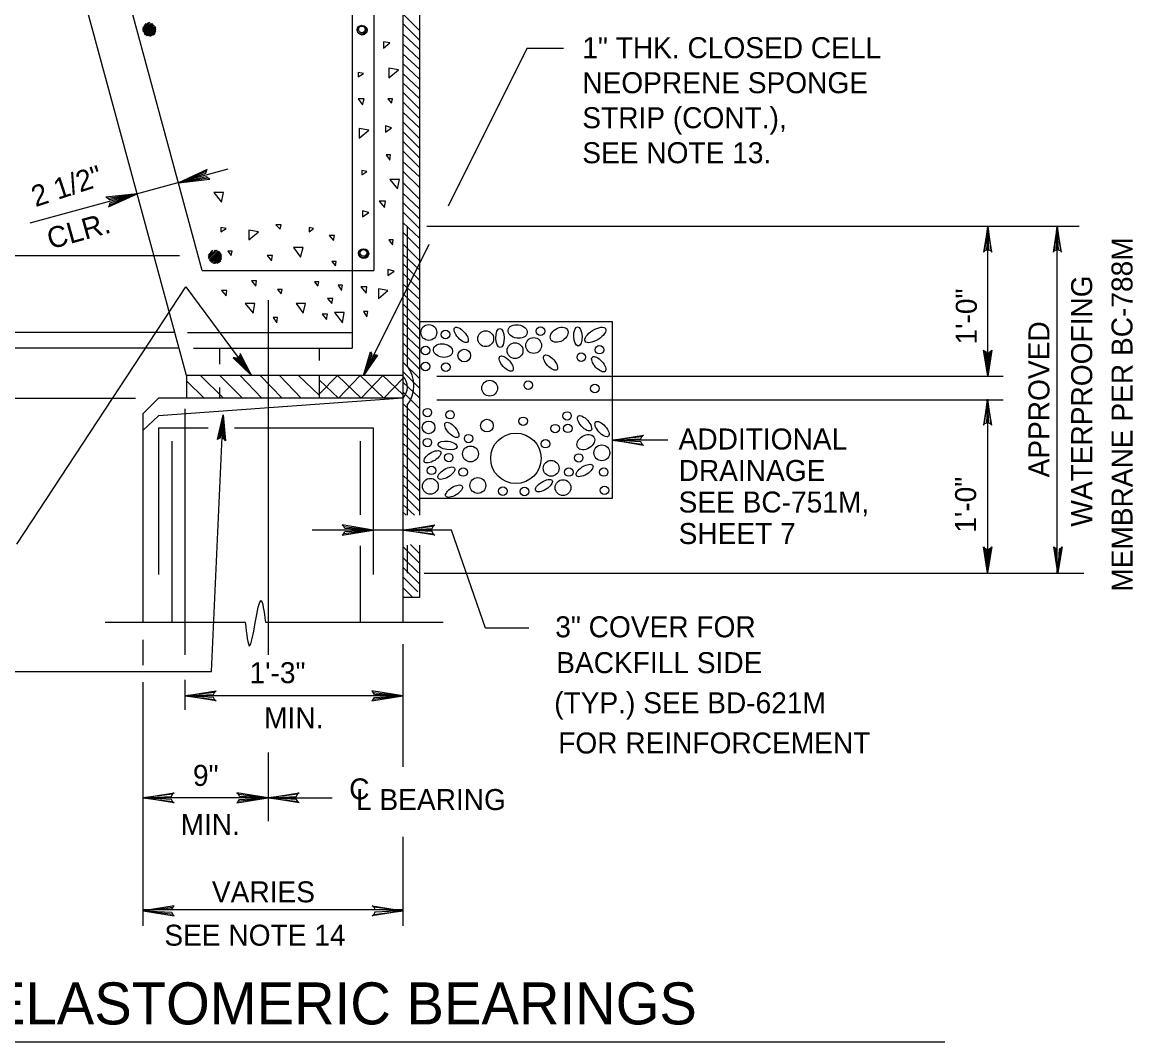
# Model space of a CAD drawing. Extents: x 640009 to 641706, y 298547 to 299735.
# Drawn here: x 640461.6 to 640620.2, y 299450.3 to 299595.9 of the extents above; entities that cross this region are included whole.
import ezdxf

# ---------------------------------------------------------------- set-up
doc = ezdxf.new("R2010")
doc.units = 0
doc.layers.add('1', color=7, linetype='Continuous')

msp = doc.modelspace()

# ---------------------------------------------------------------- linework, layer by layer
at = {"layer": '1'}
for p, q in [((640485.09, 299545.46), (640459.59, 299639.34)), ((640515.97, 299626.84), (640515.97, 299545.46)), ((640508.72, 299619.71), (640508.72, 299549.34)), ((640487.34, 299560.46), (640473.58, 299611.14)), ((640518.35, 299606.07), (640518.35, 299525.49)), ((640511.84, 299600.84), (640511.84, 299567.59)), ((640533.68, 299592.13), (640522.43, 299569.63)), ((640538.91, 299592.13), (640533.68, 299592.13)), ((640491, 299574.9), (640462.71, 299567.22)), ((640511.84, 299568.21), (640511.84, 299560.46)), ((640516.59, 299566.77), (640516.59, 299546.84)), ((640519.39, 299566.77), (640612.51, 299566.77)), ((640599.47, 299545.34), (640599.47, 299566.77)), ((640609.41, 299517.21), (640609.41, 299566.77)), ((640519.68, 299564.14), (640510.34, 299545.46)), ((640433.22, 299562.59), (640484.08, 299562.59)), ((640487.34, 299560.46), (640511.84, 299560.46)), ((640460.86, 299521.37), (640484.97, 299558.09)), ((640484.97, 299558.09), (640494.34, 299545.46)), ((640496.72, 299556.21), (640496.72, 299505.58)), ((640483.34, 299551.59), (640448.64, 299551.59)), ((640485.22, 299551.59), (640508.72, 299551.59)), ((640484.04, 299549.34), (640392.47, 299549.34)), ((640486.09, 299549.34), (640508.72, 299549.34)), ((640489.84, 299547.09), (640489.84, 299549.34)), ((640504.09, 299547.59), (640504.09, 299549.34)), ((640485.09, 299545.46), (640485.09, 299542.21)), ((640485.09, 299545.46), (640485.09, 299542.21)), ((640504.09, 299545.46), (640485.09, 299545.46)), ((640504.09, 299542.21), (640504.09, 299545.46)), ((640504.09, 299542.83), (640506.62, 299545.46)), ((640515.97, 299545.46), (640504.09, 299545.46)), ((640510.01, 299542.21), (640506.62, 299545.46)), ((640506.76, 299542.21), (640509.87, 299545.46)), ((640510.01, 299542.21), (640513.12, 299545.46)), ((640515.97, 299542.74), (640513.12, 299545.46)), ((640513.26, 299542.21), (640515.97, 299545.04)), ((640515.97, 299545.46), (640515.97, 299542.21)), ((640520.84, 299545.34), (640601.67, 299545.34)), ((640489.84, 299542.21), (640489.84, 299543.74)), ((640443.03, 299542.21), (640477.81, 299542.21)), ((640478.84, 299539.96), (640481.09, 299542.21)), ((640515.97, 299542.21), (640481.09, 299539.71)), ((640485.09, 299542.21), (640481.09, 299542.21)), ((640504.09, 299542.21), (640485.09, 299542.21)), ((640515.97, 299542.21), (640504.09, 299542.21)), ((640515.97, 299542.21), (640515.97, 299510.21)), ((640520.83, 299541.96), (640601.67, 299541.96)), ((640599.47, 299517.21), (640599.47, 299541.96)), ((640478.84, 299539.96), (640478.84, 299510.21)), ((640484.84, 299540.71), (640484.84, 299505.55)), ((640516.59, 299541.21), (640516.59, 299525.49)), ((640478.84, 299537.59), (640481.09, 299539.71)), ((640488.63, 299503.19), (640490.33, 299539.82)), ((640481.09, 299537.96), (640481.09, 299517.03)), ((640481.09, 299537.96), (640488.19, 299537.96)), ((640484.84, 299537.71), (640484.84, 299537.71)), ((640491.91, 299537.96), (640511.75, 299537.96)), ((640511.75, 299537.96), (640511.75, 299517.03)), ((640482.97, 299536.08), (640482.97, 299510.21)), ((640509.88, 299536.08), (640509.88, 299525.56)), ((640553.78, 299536.19), (640545.88, 299536.19)), ((640515.97, 299523.38), (640503.04, 299523.38)), ((640522.91, 299523.38), (640515.97, 299523.38)), ((640527.78, 299509.37), (640522.91, 299523.38)), ((640509.88, 299521.14), (640509.88, 299510.21)), ((640516.59, 299521.21), (640516.59, 299517.21)), ((640518.35, 299521.21), (640518.35, 299513.73)), ((640519, 299517.21), (640613.22, 299517.21)), ((640518.35, 299513.73), (640515.97, 299513.73)), ((640473.47, 299510.21), (640493.47, 299510.21)), ((640496.34, 299510.21), (640521.72, 299510.21)), ((640533.96, 299509.37), (640527.78, 299509.37)), ((640478.84, 299507.71), (640478.84, 299504.08)), ((640515.97, 299507.09), (640515.97, 299489.58)), ((640413.32, 299503.19), (640488.63, 299503.19)), ((640484.84, 299501.99), (640484.84, 299497.68)), ((640478.84, 299501.67), (640478.84, 299466.88)), ((640515.97, 299499.7), (640484.84, 299499.7)), ((640496.72, 299491.61), (640496.72, 299481.8)), ((640496.72, 299485.14), (640478.84, 299485.14)), ((640496.72, 299485.14), (640505.89, 299485.14)), ((640515.97, 299479.58), (640515.97, 299466.88)), ((640515.97, 299469.13), (640478.84, 299469.13)), ((640413.23, 299450.3), (640593.33, 299450.3))]:
    msp.add_line(p, q, dxfattribs=at)
for points in [[(640518.35, 299594.72), (640515.97, 299597.1)], [(640478.84, 299594.84), (640479.72, 299595.84)], [(640478.84, 299594.71), (640479.84, 299595.84)], [(640478.84, 299594.84), (640479.84, 299595.84)], [(640478.84, 299594.96), (640479.72, 299595.84)], [(640478.84, 299594.59), (640479.97, 299595.71)], [(640478.84, 299595.09), (640479.47, 299595.71)], [(640478.97, 299594.34), (640480.22, 299595.71)], [(640478.97, 299594.46), (640480.22, 299595.71)], [(640478.97, 299594.46), (640480.09, 299595.71)], [(640478.97, 299595.21), (640479.34, 299595.71)], [(640479.09, 299594.21), (640480.34, 299595.59)], [(640479.09, 299594.21), (640480.34, 299595.59)], [(640479.09, 299594.09), (640480.47, 299595.46)], [(640479.22, 299594.09), (640480.47, 299595.46)], [(640518.35, 299593.35), (640515.97, 299595.72)], [(640479.22, 299594.09), (640480.59, 299595.34)], [(640479.34, 299593.96), (640480.59, 299595.34)], [(640479.47, 299593.96), (640480.59, 299595.21)], [(640479.47, 299593.96), (640480.72, 299595.21)], [(640479.47, 299593.96), (640480.59, 299595.21)], [(640479.59, 299593.96), (640480.72, 299595.09)], [(640479.72, 299593.96), (640480.72, 299594.96)], [(640479.84, 299593.84), (640480.72, 299594.84)], [(640479.97, 299593.96), (640480.72, 299594.71)], [(640480.09, 299593.96), (640480.72, 299594.59)], [(640480.34, 299594.09), (640480.59, 299594.34)], [(640518.35, 299592), (640515.97, 299594.22)], [(640518.35, 299590.59), (640515.97, 299592.81)], [(640518.35, 299589.18), (640515.97, 299591.4)], [(640518.35, 299587.77), (640515.97, 299589.99)], [(640518.35, 299586.36), (640515.97, 299588.58)], [(640518.35, 299585), (640515.97, 299587.22)], [(640518.35, 299583.53), (640515.97, 299585.9)], [(640518.35, 299582.15), (640515.97, 299584.53)], [(640518.35, 299580.8), (640515.97, 299583.03)], [(640518.35, 299579.28), (640515.97, 299581.65)], [(640518.35, 299577.9), (640515.97, 299580.28)], [(640518.35, 299576.53), (640515.97, 299578.9)], [(640518.35, 299575.15), (640515.97, 299577.53)], [(640487.89, 299574.64), (640487.8, 299574.28), (640483.94, 299572.98), (640487.89, 299574.64), (640488.04, 299574.87), (640483.94, 299572.98), (640487.92, 299573.88), (640488.15, 299573.63), (640483.94, 299572.98), (640488.43, 299573.48), (640488.15, 299573.63)], [(640518.35, 299573.8), (640515.97, 299576.03)], [(640518.35, 299572.28), (640515.97, 299574.65)], [(640518.35, 299570.62), (640515.97, 299572.99)], [(640474.1, 299569.76), (640474.18, 299570.11), (640478.05, 299571.38), (640474.1, 299569.76), (640473.94, 299569.53), (640478.05, 299571.38), (640474.07, 299570.52), (640473.84, 299570.77), (640478.05, 299571.38), (640473.56, 299570.93), (640473.84, 299570.77)], [(640518.35, 299569.27), (640515.97, 299571.49)], [(640518.35, 299567.8), (640515.97, 299570.17)], [(640518.35, 299566.42), (640515.97, 299568.8)], [(640518.35, 299565.07), (640515.97, 299567.3)], [(640518.35, 299563.55), (640515.97, 299565.92)], [(640599.92, 299563.23), (640599.65, 299563.37), (640599.47, 299566.77), (640599.92, 299563.23), (640600.07, 299563.05), (640599.47, 299566.77), (640599.3, 299563.37), (640599.05, 299563.24), (640599.47, 299566.77), (640598.87, 299563.05), (640599.05, 299563.24)], [(640609.86, 299563.23), (640609.59, 299563.37), (640609.41, 299566.77), (640609.86, 299563.23), (640610.01, 299563.05), (640609.41, 299566.77), (640609.24, 299563.37), (640608.99, 299563.24), (640609.41, 299566.77), (640608.81, 299563.05), (640608.99, 299563.24)], [(640518.35, 299561.88), (640515.97, 299564.26)], [(640488.22, 299562.09), (640489.47, 299563.34)], [(640488.22, 299562.21), (640489.34, 299563.34)], [(640488.22, 299562.21), (640489.22, 299563.34)], [(640488.22, 299562.34), (640489.22, 299563.34)], [(640488.22, 299562.59), (640488.84, 299563.34)], [(640488.22, 299562.46), (640488.84, 299563.09)], [(640488.34, 299561.84), (640489.72, 299563.21)], [(640488.34, 299561.96), (640489.59, 299563.21)], [(640488.34, 299561.96), (640489.59, 299563.21)], [(640488.47, 299561.71), (640489.84, 299563.09)], [(640488.47, 299561.84), (640489.72, 299563.09)], [(640488.59, 299561.59), (640489.97, 299562.96)], [(640488.59, 299561.71), (640489.84, 299562.96)], [(640488.72, 299561.59), (640489.97, 299562.84)], [(640488.72, 299561.59), (640489.97, 299562.84)], [(640488.72, 299561.59), (640489.97, 299562.71)], [(640488.84, 299561.46), (640490.09, 299562.71)], [(640488.97, 299561.46), (640490.09, 299562.59)], [(640489.09, 299561.46), (640490.09, 299562.46)], [(640489.09, 299561.46), (640490.09, 299562.34)], [(640489.22, 299561.46), (640490.09, 299562.21)], [(640518.35, 299560.53), (640515.97, 299562.76)], [(640489.47, 299561.46), (640490.09, 299562.09)], [(640489.59, 299561.59), (640489.97, 299561.84)], [(640518.35, 299559.06), (640515.97, 299561.43)], [(640518.35, 299557.68), (640515.97, 299560.06)], [(640518.35, 299556.33), (640515.97, 299558.56)], [(640518.35, 299554.81), (640515.97, 299557.18)], [(640518.35, 299553.32), (640515.97, 299555.7)], [(640518.35, 299552), (640515.97, 299554.37)], [(640518.35, 299550.62), (640515.97, 299553)], [(640518.35, 299549.27), (640515.97, 299551.5)], [(640518.35, 299547.75), (640515.97, 299550.12)], [(640491.97, 299547.96), (640492.22, 299547.96), (640494.34, 299545.46), (640491.97, 299547.96), (640491.72, 299547.96), (640494.34, 299545.46), (640492.59, 299548.21), (640492.72, 299548.34), (640494.34, 299545.46), (640492.72, 299548.59), (640492.72, 299548.34)], [(640512.22, 299548.34), (640511.97, 299548.34), (640510.34, 299545.46), (640512.22, 299548.34), (640512.34, 299548.34), (640510.34, 299545.46), (640511.59, 299548.46), (640511.47, 299548.59), (640510.34, 299545.46), (640511.34, 299548.84), (640511.47, 299548.59)], [(640518.35, 299546.37), (640515.97, 299548.75)], [(640599.92, 299548.88), (640599.65, 299548.73), (640599.47, 299545.34), (640599.92, 299548.88), (640600.07, 299549.05), (640599.47, 299545.34), (640599.3, 299548.73), (640599.05, 299548.86), (640599.47, 299545.34), (640598.87, 299549.05), (640599.05, 299548.86)], [(640518.35, 299545), (640515.97, 299547.37)], [(640487.59, 299542.21), (640485.09, 299544.71)], [(640490.34, 299542.21), (640487.09, 299545.46)], [(640493.09, 299542.21), (640489.84, 299545.46)], [(640495.84, 299542.21), (640492.72, 299545.46)], [(640498.72, 299542.21), (640495.59, 299545.46)], [(640501.47, 299542.21), (640498.34, 299545.46)], [(640504.09, 299542.59), (640501.09, 299545.46)], [(640506.76, 299542.21), (640504.09, 299544.76)], [(640513.26, 299542.21), (640509.87, 299545.46)], [(640518.35, 299543.62), (640515.97, 299546)], [(640518.35, 299542.27), (640515.97, 299544.5)], [(640518.35, 299540.75), (640515.97, 299543.12)], [(640599.9, 299538.51), (640599.64, 299538.66), (640599.46, 299542.05), (640599.9, 299538.51), (640600.06, 299538.34), (640599.46, 299542.05), (640599.29, 299538.66), (640599.04, 299538.53), (640599.46, 299542.05), (640598.85, 299538.34), (640599.04, 299538.53)], [(640518.35, 299539.09), (640515.97, 299541.47)], [(640518.35, 299537.74), (640515.97, 299539.97)], [(640489.71, 299536.43), (640489.92, 299536.56), (640490.33, 299539.82), (640489.71, 299536.43), (640489.5, 299536.29), (640490.33, 299539.82), (640490.26, 299536.49), (640490.5, 299536.35), (640490.33, 299539.82), (640490.64, 299536.14), (640490.5, 299536.35)], [(640518.35, 299536.27), (640515.97, 299538.64)], [(640518.35, 299534.89), (640515.97, 299537.27)], [(640550.12, 299535.65), (640549.95, 299535.97), (640545.88, 299536.19), (640550.12, 299535.65), (640550.33, 299535.47), (640545.88, 299536.19), (640549.95, 299536.39), (640550.11, 299536.69), (640545.88, 299536.19), (640550.33, 299536.91), (640550.11, 299536.69)], [(640518.35, 299533.54), (640515.97, 299535.77)], [(640518.35, 299532.02), (640515.97, 299534.39)], [(640518.35, 299530.35), (640515.97, 299532.73)], [(640518.35, 299529), (640515.97, 299531.23)], [(640518.35, 299527.53), (640515.97, 299529.9)], [(640518.35, 299526.07), (640515.97, 299528.45)], [(640516.42, 299525.49), (640515.9, 299525.98)], [(640517.62, 299525.49), (640515.97, 299527.03)], [(640507.51, 299522.85), (640507.68, 299523.16), (640511.75, 299523.38), (640507.51, 299522.85), (640507.3, 299522.66), (640511.75, 299523.38), (640507.68, 299523.58), (640507.53, 299523.89), (640511.75, 299523.38), (640507.3, 299524.11), (640507.53, 299523.89)], [(640520.31, 299522.85), (640520.14, 299523.16), (640516.07, 299523.38), (640520.31, 299522.85), (640520.52, 299522.66), (640516.07, 299523.38), (640520.14, 299523.58), (640520.3, 299523.89), (640516.07, 299523.38), (640520.52, 299524.11), (640520.3, 299523.89)], [(640518.35, 299518.64), (640515.97, 299521.01)], [(640518.41, 299519.97), (640517.08, 299521.3)], [(640599.9, 299520.79), (640599.64, 299520.64), (640599.46, 299517.25), (640599.9, 299520.79), (640600.06, 299520.96), (640599.46, 299517.25), (640599.29, 299520.64), (640599.04, 299520.77), (640599.46, 299517.25), (640598.85, 299520.96), (640599.04, 299520.77)], [(640609.96, 299520.79), (640609.7, 299520.64), (640609.51, 299517.25), (640609.96, 299520.79), (640610.12, 299520.96), (640609.51, 299517.25), (640609.35, 299520.64), (640609.09, 299520.77), (640609.51, 299517.25), (640608.91, 299520.96), (640609.09, 299520.77)], [(640518.2, 299517.25), (640515.97, 299519.48)], [(640518.35, 299515.71), (640515.97, 299518.08)], [(640518.13, 299514.54), (640515.97, 299516.7)], [(640517.39, 299513.73), (640515.97, 299515.15)], [(640489.09, 299499.16), (640488.92, 299499.48), (640484.84, 299499.7), (640489.09, 299499.16), (640489.3, 299498.97), (640484.84, 299499.7), (640488.92, 299499.9), (640489.07, 299500.2), (640484.84, 299499.7), (640489.3, 299500.42), (640489.07, 299500.2)], [(640511.73, 299499.16), (640511.9, 299499.48), (640515.97, 299499.7), (640511.73, 299499.16), (640511.52, 299498.97), (640515.97, 299499.7), (640511.9, 299499.9), (640511.74, 299500.2), (640515.97, 299499.7), (640511.52, 299500.42), (640511.74, 299500.2)], [(640483.09, 299484.61), (640482.92, 299484.92), (640478.84, 299485.14), (640483.09, 299484.61), (640483.3, 299484.42), (640478.84, 299485.14), (640482.92, 299485.34), (640483.07, 299485.65), (640478.84, 299485.14), (640483.3, 299485.87), (640483.07, 299485.65)], [(640492.48, 299484.61), (640492.65, 299484.92), (640496.72, 299485.14), (640492.48, 299484.61), (640492.27, 299484.42), (640496.72, 299485.14), (640492.65, 299485.34), (640492.49, 299485.65), (640496.72, 299485.14), (640492.27, 299485.87), (640492.49, 299485.65)], [(640500.96, 299484.61), (640500.79, 299484.92), (640496.72, 299485.14), (640500.96, 299484.61), (640501.17, 299484.42), (640496.72, 299485.14), (640500.79, 299485.34), (640500.95, 299485.65), (640496.72, 299485.14), (640501.17, 299485.87), (640500.95, 299485.65)], [(640483.13, 299469.53), (640482.96, 299469.22), (640478.89, 299468.99), (640483.13, 299469.53), (640483.34, 299469.72), (640478.89, 299468.99), (640482.96, 299468.79), (640483.12, 299468.49), (640478.89, 299468.99), (640483.34, 299468.27), (640483.12, 299468.49)], [(640511.81, 299469.53), (640511.98, 299469.22), (640516.05, 299468.99), (640511.81, 299469.53), (640511.59, 299469.72), (640516.05, 299468.99), (640511.98, 299468.79), (640511.82, 299468.49), (640516.05, 299468.99), (640511.59, 299468.27), (640511.82, 299468.49)]]:
    msp.add_lwpolyline(points, dxfattribs=at)
for points in [[(640513.22, 299592.21), (640514.09, 299592.96), (640513.22, 299593.09)], [(640513.97, 299587.96), (640515.34, 299589.09), (640513.97, 299589.34)], [(640509.59, 299588.09), (640510.34, 299588.59), (640509.59, 299588.71)], [(640509.59, 299584.96), (640510.22, 299584.09), (640510.47, 299584.96)], [(640513.84, 299584.96), (640514.34, 299584.34), (640514.47, 299584.96)], [(640509.72, 299579.34), (640511.09, 299580.46), (640509.72, 299580.71)], [(640513.47, 299580.21), (640514.34, 299580.84), (640513.47, 299581.09)], [(640513.59, 299576.96), (640514.09, 299576.21), (640514.22, 299576.96)], [(640510.09, 299574.09), (640510.84, 299574.59), (640510.09, 299574.71)], [(640514.09, 299573.46), (640515.22, 299572.09), (640515.47, 299573.46)], [(640488.97, 299571.59), (640490.09, 299570.21), (640490.34, 299571.59)], [(640512.59, 299570.34), (640513.34, 299569.46), (640513.47, 299570.34)], [(640510.22, 299568.09), (640511.09, 299568.71), (640510.22, 299568.96)], [(640497.84, 299566.96), (640498.47, 299566.34), (640498.59, 299566.96)], [(640489.97, 299565.96), (640490.72, 299566.46), (640489.97, 299566.59)], [(640493.97, 299564.84), (640495.34, 299565.96), (640493.97, 299566.21)], [(640502.59, 299565.96), (640503.22, 299566.46), (640502.59, 299566.59)], [(640505.47, 299565.46), (640506.09, 299564.71), (640506.22, 299565.46)], [(640500.34, 299563.71), (640501.34, 299562.34), (640501.72, 299563.71)], [(640513.97, 299564.84), (640514.47, 299564.09), (640514.59, 299564.84)], [(640490.97, 299563.21), (640491.47, 299562.59), (640491.59, 299563.21)], [(640496.59, 299562.59), (640497.22, 299561.84), (640497.34, 299562.59)], [(640505.84, 299561.71), (640506.34, 299561.09), (640506.47, 299561.71)], [(640513.84, 299559.71), (640514.72, 299560.34), (640513.84, 299560.59)], [(640494.34, 299558.96), (640494.97, 299558.21), (640495.09, 299558.96)], [(640490.09, 299557.59), (640490.72, 299556.84), (640490.84, 299557.59)], [(640498.09, 299557.71), (640498.59, 299557.09), (640498.72, 299557.71)], [(640503.34, 299558.84), (640503.84, 299558.21), (640503.97, 299558.84)], [(640506.72, 299558.34), (640507.22, 299557.59), (640507.34, 299558.34)], [(640509.97, 299558.09), (640510.72, 299557.21), (640510.84, 299558.09)], [(640512.47, 299556.46), (640513.84, 299557.59), (640512.47, 299557.84)], [(640505.22, 299556.46), (640505.84, 299555.71), (640505.97, 299556.46)], [(640493.47, 299555.71), (640494.59, 299554.34), (640494.84, 299555.71)], [(640500.72, 299555.71), (640501.72, 299554.34), (640502.09, 299555.71)], [(640504.47, 299554.21), (640505.09, 299553.46), (640505.22, 299554.21)], [(640506.22, 299554.46), (640507.34, 299552.96), (640507.59, 299554.46)], [(640510.34, 299554.59), (640510.84, 299553.84), (640510.97, 299554.59)], [(640497.47, 299553.71), (640497.97, 299552.96), (640498.09, 299553.71)], [(640545.88, 299553.11), (640518.35, 299553.11), (640518.35, 299527.92), (640545.88, 299527.92)]]:
    msp.add_lwpolyline(points, close=True, dxfattribs=at)
for centre, radius in [((640510.06, 299594.82), 0.636), ((640510.17, 299594.76), 0.693), ((640510.12, 299594.88), 0.474), ((640510.29, 299562.9), 0.636), ((640510.4, 299562.84), 0.693), ((640510.35, 299562.95), 0.474), ((640519.68, 299551.6), 1.13), ((640522.05, 299551.3), 0.605), ((640527.8, 299550.7), 1.13), ((640535.63, 299551.77), 0.605), ((640519.2, 299549.02), 0.605), ((640531.99, 299549), 1.13), ((640534.65, 299549.74), 1.13), ((640544.05, 299549.13), 0.605), ((640524.74, 299548.3), 0.9), ((640541.44, 299548.06), 0.605), ((640519.2, 299546.74), 0.605), ((640522.1, 299546.63), 0.605), ((640528.36, 299543.63), 1.13), ((640533.88, 299544.07), 0.605), ((640543.39, 299543.59), 0.605), ((640519.47, 299540.15), 0.605), ((640522.71, 299539.85), 0.605), ((640539.42, 299539.67), 0.605), ((640519.64, 299538.04), 0.9), ((640527.97, 299538.29), 0.9), ((640533.15, 299538.91), 0.605), ((640537.71, 299537.86), 0.605), ((640539.52, 299537.9), 0.605), ((640525.36, 299536.44), 0.605), ((640532.11, 299533.62), 3.6), ((640519.47, 299535.87), 0.605), ((640525.63, 299534.25), 1.13), ((640536.33, 299535.7), 0.605), ((640544.38, 299534.41), 1.13), ((640522.52, 299533.72), 0.605), ((640541.08, 299533.68), 0.605), ((640520.07, 299531.9), 0.605), ((640524.58, 299531.66), 0.605), ((640537.15, 299532.2), 1.13), ((640539.66, 299531.66), 0.605), ((640544.65, 299531.66), 0.605), ((640519.9, 299529.63), 1.13), ((640526.67, 299529.75), 1.13), ((640538.84, 299529.44), 1.13), ((640530.24, 299528.94), 0.605), ((640533.34, 299528.88), 0.605), ((640544.76, 299529.05), 0.605)]:
    msp.add_circle(centre, radius, dxfattribs=at)
msp.add_arc((640513.09, 299544.01), 4.47, 321.0382, 38.9618, dxfattribs=at)
for centre, major_axis, ratio in [((640532.36, 299551.73), (1.36, -0.2), 0.696126), ((640524.3, 299551.25), (0.91, -1.02), 0.438009), ((640529.84, 299550.8), (0.04, -1.37), 0.438009), ((640538.29, 299551.27), (1.17, 0.72), 0.696126), ((640540.96, 299551.03), (0.04, -1.37), 0.438009), ((640543.46, 299551.24), (1.46, 0.9), 0.438009), ((640521.7, 299549.01), (1.36, -0.2), 0.696126), ((640530.73, 299547.15), (0.91, -1.02), 0.438009), ((640537.06, 299547.29), (0.91, -1.02), 0.438009), ((640543.94, 299547.06), (0.91, -1.02), 0.438009), ((640522.96, 299537.67), (0.91, -1.02), 0.438009), ((640541.92, 299538.62), (0.91, -1.02), 0.438009), ((640544.41, 299537.79), (0.91, -1.02), 0.438009), ((640542.09, 299535.93), (1.17, 0.72), 0.696126), ((640522.35, 299535.46), (1.36, -0.2), 0.438009), ((640520.2, 299533.84), (1.17, 0.72), 0.438009), ((640522.18, 299531.5), (1.17, 0.72), 0.438009), ((640541.91, 299531.88), (1.17, 0.72), 0.438009), ((640536.11, 299529.72), (1.17, 0.72), 0.438009), ((640523.28, 299528.93), (1.17, 0.72), 0.438009)]:
    msp.add_ellipse(centre, major_axis=major_axis, ratio=ratio, dxfattribs=at)
msp.add_ellipse((640513.8, 299543.79), major_axis=(2.81, 0), ratio=0.9, start_param=5.608799, end_param=6.961087, dxfattribs=at)
msp.add_spline([(640493.47, 299510.21), (640494.09, 299506.84), (640495.72, 299513.34), (640496.34, 299510.21)], degree=3, dxfattribs=at)

# ---------------------------------------------------------------- texts
for s, height, p in [('1" THK. CLOSED CELL', 3, (640541.59, 299590.76)), ('NEOPRENE SPONGE ', 3, (640541.59, 299585.76)), ('STRIP (CONT.),', 3, (640541.59, 299580.76)), ('SEE NOTE 13.', 3, (640541.59, 299575.76)), ('ADDITIONAL', 3, (640555.34, 299534.88)), ('DRAINAGE', 3, (640555.34, 299530.38)), ('SEE BC-751M,', 3, (640555.34, 299525.88)), ('SHEET 7', 3, (640555.34, 299521.38)), ('3" COVER FOR', 3, (640537.73, 299508.06)), ('BACKFILL SIDE', 3, (640537.87, 299502.94)), ('1\'-3"', 3, (640494.08, 299501.51)), ('(TYP.) SEE BD-621M', 3, (640537.58, 299497.21)), ('MIN.', 3, (640496.16, 299495.07)), ('FOR REINFORCEMENT', 3, (640538.15, 299491.47)), ('9"', 3, (640486, 299486.84)), ('C', 3, (640508.31, 299484.91)), ('L BEARING', 3, (640509.28, 299483.39)), ('MIN.', 3, (640484.24, 299479.83)), ('VARIES', 3, (640488.71, 299470.21)), ('SEE NOTE 14', 3, (640481.92, 299464.02)), ('SECTION - ELASTOMERIC BEARINGS', 6, (640413.95, 299452.78))]:
    msp.add_text(s, height=height, dxfattribs=at).set_placement(p)
for s, rotation, p in [('2 1/2"', 18.1801, (640463.52, 299569.48)), ('CLR.', 15.574, (640465.66, 299563.45)), ('MEMBRANE PER BC-788M', 90, (640620.15, 299514.57)), ('WATERPROOFING', 90, (640614.39, 299523.86)), ('1\'-0"', 90, (640597.92, 299549.88)), ('APPROVED', 90, (640608.29, 299530.89)), ('1\'-0"', 90, (640597.82, 299523))]:
    msp.add_text(s, height=3, rotation=rotation, dxfattribs=at).set_placement(p)

doc.saveas('drawing.dxf')
